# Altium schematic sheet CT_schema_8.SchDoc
size 382 x 278 mm
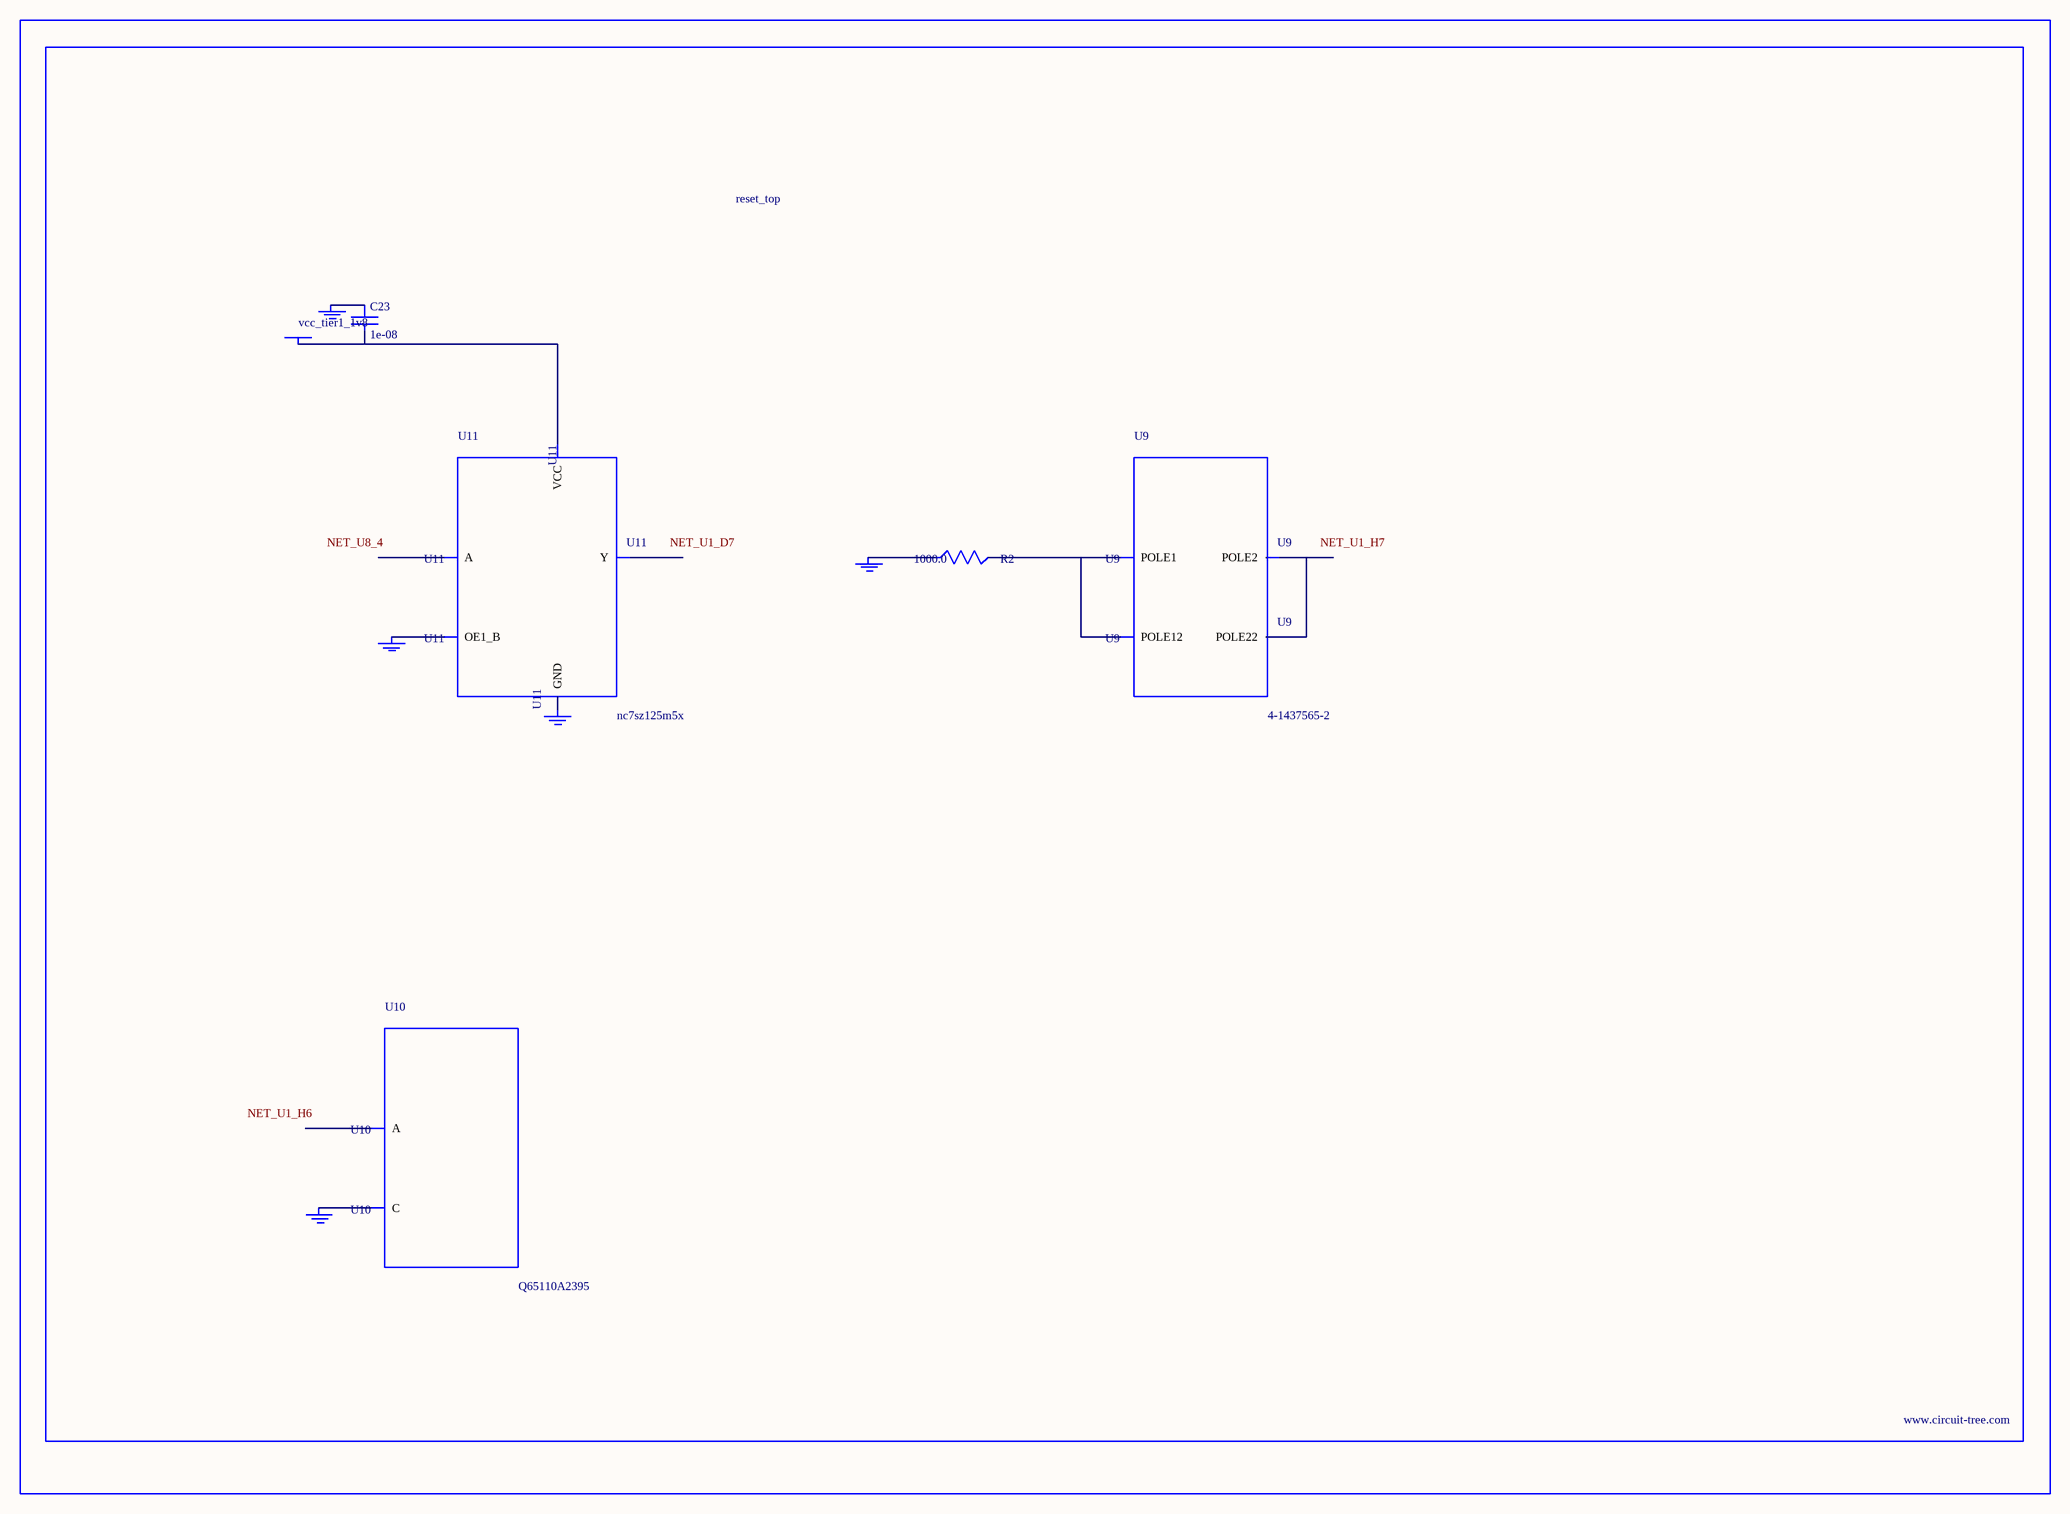
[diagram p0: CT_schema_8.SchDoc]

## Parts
BORDER7  (no value)
C23  1e-08  [C0402]
GND_INSTANCE_7_0  (no value)
GND_INSTANCE_7_1  (no value)
GND_INSTANCE_7_2  (no value)
GND_INSTANCE_7_3  (no value)
GND_INSTANCE_7_4  (no value)
POWER_INSTANCE_7_0  vcc_tier1_1v8
R2  1000.0  [R0603]
U9  4-1437565-2  [SW_4-1437565-2]
U10  Q65110A2395  [LGM67K-G1J2-24-Z]
U11  nc7sz125m5x  [NC7SZ125M5X]

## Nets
NetC23_1: C23.1 GND_INSTANCE_7_2.0(GND)
NetC23_2: C23.2 POWER_INSTANCE_7_0.0(PWR) U11.5(VCC)
NetGND_INSTANCE_7_0_0: GND_INSTANCE_7_0.0(GND) R2.1
NetGND_INSTANCE_7_1_0: GND_INSTANCE_7_1.0(GND) U10.C
NetGND_INSTANCE_7_3_0: GND_INSTANCE_7_3.0(GND) U11.1(OE1_B)
NetGND_INSTANCE_7_4_0: GND_INSTANCE_7_4.0(GND) U11.3(GND)
NetR2_2: R2.2 U9.1(POLE1) U9.2(POLE12)
NetU9_3: U9.3(POLE2) U9.4(POLE22)

Not connected (* = marked no-connect by the designer): U10 A; U11 2(A) 4(Y)

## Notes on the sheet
- Labels drawn without touching a wire or pin: NET_U1_D7, NET_U1_H6, NET_U1_H7, NET_U8_4

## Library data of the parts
BORDER7 = BORDER_PAGE7
C23 = C0402C103K3RAC
GND_INSTANCE_7_0-GND_INSTANCE_7_4 = GND
POWER_INSTANCE_7_0 = PWR
R2 = RC0603JR-071KL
